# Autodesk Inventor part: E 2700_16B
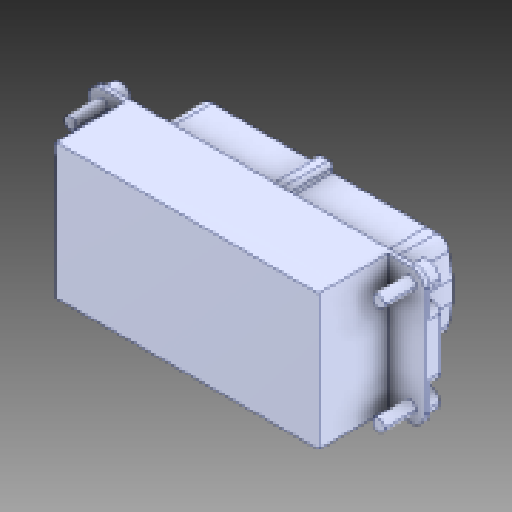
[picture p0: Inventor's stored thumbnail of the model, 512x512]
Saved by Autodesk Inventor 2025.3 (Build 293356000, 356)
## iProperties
Created: 2025-05
Part Number: E 2700_16B
Material: Všeobecné
Document SubType Name: Modeling
Designer: Patrik
Density: 1 g/cm^3
Appearance: Výchozí
Description: Vložka s dutinkami, šroubovací
Stock Number: E 2700_16B
Mass: 62.5457 g
Surface Area: 179.412 cm^2
Volume: 62.5457 cm^3
Sending System: KiM GmbH
Major Version: 4.0
Minor Version: 0.0
Format Version: 0.0
Product Id: KiM GmbH
Hersteller: Meusburger
Material: Polycarbonat _ Polycarbonate
Bestellnummer: E2700/16B
Teilenummer: E2700/16B
Beschreibung: Buchseneinsatz mit Schraubanschluss _ Female insert with threaded connection
Author: Patrik
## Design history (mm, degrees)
feature "E 2700_16B_1_1:1"
sketch "Náčrt1"
  geometry: L1 (0, 34)-(0, 0); L2 (0, 0)-(66.1, 0); L3 (66.1, 0)-(66.1, 34); L4 (66.1, 34)-(0, 34)
extrude "Vysunutí1" join sketch "Náčrt1" distance "d0" = 1; taper "d1" = 0 deg
node "Těleso1"
